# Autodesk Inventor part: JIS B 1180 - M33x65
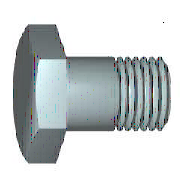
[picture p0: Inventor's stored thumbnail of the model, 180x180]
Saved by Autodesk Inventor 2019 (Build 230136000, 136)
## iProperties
Created: 2017-02
Part Number: JIS B 1180 - M33x65
Material: 鋼、軟鋼
Description: 全ねじ六角ボルト、 部品等級 C
Document SubType Name: Modeling
Standard: JIS B 1180
Designer: shimont
Standard Revision: 2014
Standards Organization: JIS
Language: ja-JP
Size Designation: M33x65
Categories: <MemberInstance><Categories><Category DisplayName="締結器具" InternalName="e4da775c-781d-43d5-af7c-5136215cf5a6" Mnemonic="FSTN"><Category DisplayName="ボルト" Interna
Density: 7.85 g/cm^3
Appearance: 半つや出し
Mass: 791.237 g
Surface Area: 144.504 cm^2
Volume: 100.794 cm^3
IsCustomPart: 0
Author: shimont
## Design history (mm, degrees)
node "WorkPlane1"
node "WorkPoint1"
node "MSC_A1"
node "MSC_PF1"
node "MSC_PT1"
body "Solid1"
node "スケッチ1"
sketch "スケッチ2"
  geometry: L1 (-25, 14.434)-(-25, -14.434); L2 (0, 28.867)-(-25, 14.434); L3 (25, 14.434)-(0, 28.867); L4 (25, -14.434)-(25, 14.434); L5 (0, -28.867)-(25, -14.434); L6 (-25, -14.434)-(0, -28.867); C1 r 25 at (0, 0); 1 further point
  constraints: 12 end point, 6 tangent, 2 parallel, 2 vertical, 1 centre point
  dimensions: "d1" = 50 diameter of C1 (= ParS); "d29" = 0 distance of point (0, 0) C1.centre; "d30" = 0 distance of C1.centre point (0, 0)
extrude "押し出し1" new body sketch "スケッチ2" distance "d6" = 21 (= ParK); taper "d7" = 0 deg
revolve "回転1" stored, may be unused: angle "d14" = 360 deg
revolve "回転2" stored, may be unused: angle "d21" = 360 deg
chamfer "面取り1" distance "d22" = 1.75 (= 0.5 x PTC); stored, may be unused: second distance "d23" = 1.75 (= 0.5 x PTC), angle "d39" = 45 deg
fillet "フィレット1" dims "d24" = 1 (= r)
feature "ねじ1" dims "d32" = 0, "b" = 58 (= NLG - 2 x PTC)
sketch "スケッチ3"
  geometry: L1 (25, 21)-(28.967, 21); L2 (28.967, 18.71)-(25, 21); L3 (28.967, 21)-(28.967, 18.71); L4 (0, -4.2)-(0, 25.2) reference; L5 (28.867, 0)-(28.867, 21) reference
  constraints: 6 end point, 1 horizontal, 1 vertical
  dimensions: "d25" = 0.1 distance between parallel lines of L5 L3; "d26" = 0 distance from line of L5.end L1; "d27" = 60 deg angle of L3 L2; "d28" = 25 distance from line of L4 L1.start (= 0.5 x ParS)
sketch "スケッチ4"
  geometry: L1 (0, -65)-(0, 0); L2 (-16.5, -65)-(0, -65); L3 (-16.5, 0)-(-16.5, -65); L4 (0, 0)-(-16.5, 0); L5 (0, -65)-(0, 0); L6 (-19.8, 0)-(3.3, 0) reference; L7 (0, -78)-(0, 13) reference
  constraints: 10 end point, 2 horizontal, 2 vertical
  dimensions: "d18" = 16.5 distance of L1.start L2.start (= 0.5 x NND); "d20" = 65 distance of L3.start L2.start (= NLG); "d33" = 0 distance between parallel lines of L7 L1; "d34" = 0 distance between parallel lines of L6 L4
other parameters: "NND" = 33 [user parameter; used in 2 equation terms], "NLG" = 65 [user parameter; used in 2 equation terms], "PTC" = 3.5 [user parameter; used in 3 equation terms], "ParK" = 21 [user parameter; used in 1 equation term], "ParS" = 50 [user parameter; used in 3 equation terms], "msp_es" = 28.86836 (= 0.577367 x ParS) [user parameter], "r" = 1 [user parameter; used in 1 equation term], "d2" = 15 (derived), "d4" = 17.32102 (derived), "d8" = 15 (derived), "d10" = 0 (derived), "d12" = 30 deg (derived), "d15" = 0 (derived), "d37" = 0, "d38" = 0, "d40" = 0, "d41" = 0, "d42" = 0, "THREADDIA" = 33 (= NND) [user parameter]
